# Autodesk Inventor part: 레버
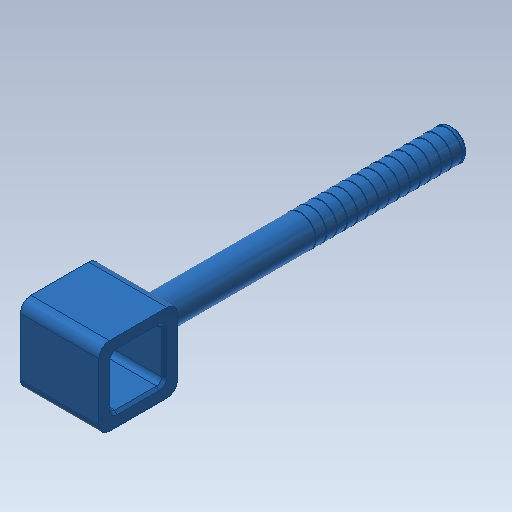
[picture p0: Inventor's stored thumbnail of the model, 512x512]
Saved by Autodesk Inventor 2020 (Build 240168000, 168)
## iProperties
Created: 2015-12
Part Number: 레버
Material: 스테인리스강
Document SubType Name: Modeling
Designer: mduedu
Density: 8.08 g/cm^3
Mass: 28.4605 g
Surface Area: 28.1796 cm^2
Volume: 3.52234 cm^3
Appearance: 청록색
Author: mduedu
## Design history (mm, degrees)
sketch "스케치1"
  geometry: C1 r 3 at (0, 0); 1 further point
  constraints: 1 centre point, 1 coincident
  dimensions: "d0" = 6 diameter of C1
extrude "돌출1" new body sketch "스케치1" distance "d1" = 60; taper "d2" = 0 deg
sketch "스케치5"
  geometry: L1 (-7.5, -7.5)-(7.5, -7.5); L2 (7.5, -7.5)-(7.5, 7.5); L3 (7.5, 7.5)-(-7.5, 7.5); L4 (-7.5, 7.5)-(-7.5, -7.5); L5 (-7.5, -7.5)-(7.5, 7.5); L6 (7.5, -7.5)-(-7.5, 7.5); C1 r 3 at (0, 0) reference
  constraints: 12 end point, 2 midpoint, 2 parallel, 2 perpendicular, 1 horizontal
  dimensions: "d24" = 15 distance of L2.end L3.end
extrude "돌출2" join sketch "스케치5" distance "d26" = 15; taper "d27" = 0 deg
chamfer "모따기1" distance "d7" = 0.5; stored, may be unused: second distance "d8" = 2, angle "d9" = 45 deg
fillet "모깎기2" dims "d11" = 1
sketch "스케치4"
  geometry: L1 (-60, -2.5)-(-60, 2.5) reference; L2 (-60, 0)-(0, 0); L3 (-1, 3)-(-59.5, 3) reference; L4 (-59, 3)-(-58.9, 3); L5 (-58.9, 3)-(-58.9, 2.9); L6 (-58.9, 2.9)-(-59, 2.9); L7 (-59, 2.9)-(-59, 3)
  constraints: 10 end point, 2 parallel, 2 perpendicular, 1 horizontal, 1 midpoint, 1 point on line
  dimensions: "d17" = 1 distance between parallel lines of L7 L1; "d18" = 0.1 distance of L5.end L6.end; "d19" = 0.1 distance of L4.end L5.end
revolve "회전3" sketch "스케치4" stored, may be unused: angle "d20" = 90 deg
sketch "스케치6"
  geometry: L1 (0, 0)-(15, 0) reference; L2 (15, 15)-(15, 0) reference; L3 (0, 15)-(15, 15) reference; L4 (7.5, 15)-(7.5, 0); L5 (0, 7.5)-(15, 7.5); L6 (2.5, 2.5)-(12.5, 2.5); L7 (12.5, 2.5)-(12.5, 12.5); L8 (12.5, 12.5)-(2.5, 12.5); L9 (2.5, 12.5)-(2.5, 2.5); L10 (2.5, 2.5)-(12.5, 12.5); L11 (12.5, 2.5)-(2.5, 12.5); 1 further point
  constraints: 16 end point, 6 midpoint, 2 parallel, 2 perpendicular, 1 horizontal
  dimensions: "d29" = 10 distance of L7.end L8.end; "d31" = 2.5 distance between parallel lines of L8 L3 (derived)
extrude "돌출3" cut sketch "스케치6" extent not by distance; stored distance "d32" = 15; taper "d33" = 0 deg
fillet "모깎기3" dims "d34" = 2, "d35" = 1
chamfer "모따기2" distance "d36" = 0.5; stored, may be unused: second distance "d37" = 2, angle "d38" = 45 deg
node "솔리드1"
pattern_linear "직사각형 패턴1" dims "d23" = 2
